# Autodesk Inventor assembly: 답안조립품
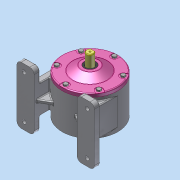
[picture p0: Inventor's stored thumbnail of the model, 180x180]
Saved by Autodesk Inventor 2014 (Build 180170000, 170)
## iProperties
Created: 2025-12
Part Number: 답안조립품
Document SubType Name: Assembly
Designer: dg
Author: dg
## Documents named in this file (17)
- C:\Users\dg\Desktop\751203V1012\답안조립품.iam
- C:\Users\dg\Desktop\751203V1012\본체.ipt
- C:\Users\dg\Desktop\751203V1012\가져온 구성요소\깊은 홈 볼 베어링 6004\깊은 홈 볼 베어링 6004.ipt
- C:\Users\dg\Desktop\751203V1012\가져온 구성요소\기어 축\기어 축.ipt
- C:\Users\dg\Desktop\751203V1012\가져온 구성요소\C형 멈춤링 구멍용 42\C형 멈춤링 구멍용 42.ipt
- C:\Users\dg\Desktop\751203V1012\가져온 구성요소\칼라 1\칼라 1.ipt
- C:\Users\dg\Desktop\751203V1012\가져온 구성요소\평행 키 6x6x16\평행 키 6x6x16.ipt
- C:\Users\dg\Desktop\751203V1012\가져온 구성요소\구동 기어\구동 기어.ipt
- C:\Users\dg\Desktop\751203V1012\가져온 구성요소\엔드 캡\엔드 캡.ipt
- C:\Users\dg\Desktop\751203V1012\가져온 구성요소\6각 구멍붙이 볼트 M4x10\6각 구멍붙이 볼트 M4x10.ipt
- C:\Users\dg\Desktop\751203V1012\가져온 구성요소\출력 축\출력 축.ipt
- C:\Users\dg\Desktop\751203V1012\가져온 구성요소\종동 기어\종동 기어.ipt
- C:\Users\dg\Desktop\751203V1012\가져온 구성요소\칼라 2\칼라 2.ipt
- C:\Users\dg\Desktop\751203V1012\가져온 구성요소\커버\커버.ipt
- C:\Users\dg\Desktop\751203V1012\가져온 구성요소\깊은 홈 볼 베어링 6005\깊은 홈 볼 베어링 6005.ipt
- C:\Users\dg\Desktop\751203V1012\가져온 구성요소\오일 실 25 40 8\오일 실 25 40 8.ipt
- C:\Users\dg\Desktop\751203V1012\가져온 구성요소\6각 머리 볼트 M8x20\6각 머리 볼트 M8x20.ipt
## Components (9 placed, 4 different names)
1. C형 멈춤링 구멍용 42:1
2. 구동 기어:1
3. 6각 구멍붙이 볼트 M4x10:1
4. 6각 머리 볼트 M8x20:1
5. 6각 머리 볼트 M8x20:2
6. 6각 머리 볼트 M8x20:3
7. 6각 머리 볼트 M8x20:4
8. 6각 머리 볼트 M8x20:5
9. 6각 머리 볼트 M8x20:6
